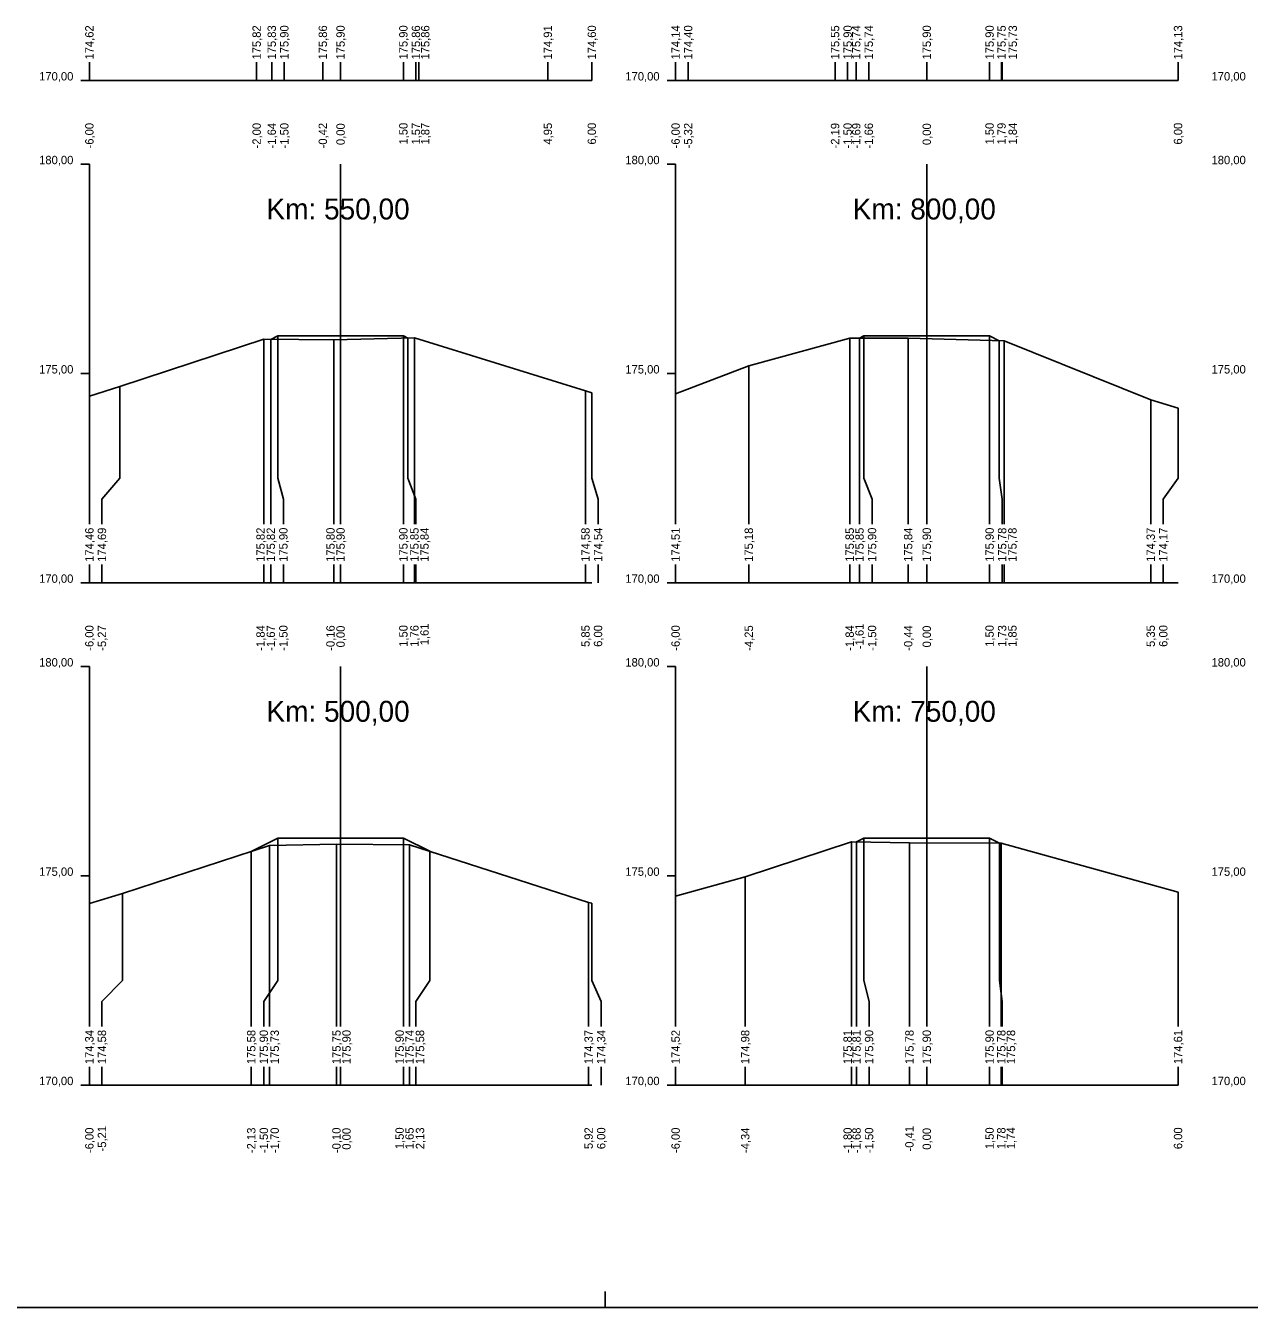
# Model space of a CAD drawing. Extents: x -614174 to -599765, y -1185887 to -1181080.
# Drawn here: x -612663.55 to -612634.33, y -1184252.54 to -1184221.92 of the extents above; entities that cross this region are included whole.
import ezdxf

# ---------------------------------------------------------------- set-up
doc = ezdxf.new("R2010")
doc.units = 0
for name, color, linetype in [('11', 7, 'Continuous'), ('16', 7, 'Continuous'), ('21', 7, 'Continuous'), ('28', 7, 'Continuous'), ('59', 7, 'Continuous'), ('8', 7, 'Continuous'), ('návrh', 7, 'Continuous')]:
    doc.layers.add(name, color=color, linetype=linetype)

msp = doc.modelspace()

# ---------------------------------------------------------------- linework, layer by layer
for points in [[(-612662.029, -1184230.778), (-612661.299, -1184230.541), (-612657.865, -1184229.416), (-612656.188, -1184229.431), (-612654.266, -1184229.385), (-612650.181, -1184230.651), (-612650.029, -1184230.697)], [(-612657.696, -1184229.418), (-612657.53, -1184229.335), (-612656.03, -1184229.335), (-612654.53, -1184229.335), (-612654.421, -1184229.389)], [(-612657.696, -1184229.418), (-612657.696, -1184229.418), (-612657.696, -1184229.418)], [(-612657.53, -1184229.335), (-612657.53, -1184229.335)], [(-612656.03, -1184229.335), (-612656.03, -1184229.335)], [(-612654.53, -1184229.335), (-612654.53, -1184229.335)], [(-612648.029, -1184230.72), (-612646.281, -1184230.054), (-612643.871, -1184229.388), (-612642.474, -1184229.392), (-612640.178, -1184229.453), (-612636.682, -1184230.863), (-612636.029, -1184231.066)], [(-612643.637, -1184229.388), (-612643.53, -1184229.335), (-612642.03, -1184229.335), (-612640.53, -1184229.335), (-612640.3, -1184229.45)], [(-612643.637, -1184229.388), (-612643.637, -1184229.388), (-612643.637, -1184229.388)], [(-612643.53, -1184229.335), (-612643.53, -1184229.335)], [(-612642.03, -1184229.335), (-612642.03, -1184229.335)], [(-612640.53, -1184229.335), (-612640.53, -1184229.335)], [(-612662.029, -1184242.896), (-612661.238, -1184242.657), (-612657.728, -1184241.509), (-612656.128, -1184241.479), (-612654.384, -1184241.494), (-612650.106, -1184242.868), (-612650.029, -1184242.891)], [(-612658.163, -1184241.651), (-612657.53, -1184241.335), (-612656.03, -1184241.335), (-612654.53, -1184241.335), (-612653.9, -1184241.649)], [(-612657.53, -1184241.335), (-612657.53, -1184241.335)], [(-612656.03, -1184241.335), (-612656.03, -1184241.335)], [(-612654.53, -1184241.335), (-612654.53, -1184241.335)], [(-612648.029, -1184242.717), (-612646.366, -1184242.257), (-612643.825, -1184241.421), (-612642.444, -1184241.449), (-612640.25, -1184241.455), (-612636.029, -1184242.628)], [(-612643.708, -1184241.424), (-612643.53, -1184241.335), (-612642.03, -1184241.335), (-612640.53, -1184241.335), (-612640.289, -1184241.455)], [(-612643.708, -1184241.424), (-612643.708, -1184241.424), (-612643.708, -1184241.424)], [(-612643.53, -1184241.335), (-612643.53, -1184241.335)], [(-612642.03, -1184241.335), (-612642.03, -1184241.335)], [(-612640.53, -1184241.335), (-612640.53, -1184241.335)], [(-612658.163, -1184241.651), (-612658.163, -1184241.651), (-612658.163, -1184241.651)]]:
    msp.add_lwpolyline(points)
at = {"layer": '11'}
for points in [[(-612662.029, -1184222.794), (-612662.029, -1184223.234)], [(-612658.034, -1184222.794), (-612658.034, -1184223.234)], [(-612657.673, -1184222.794), (-612657.673, -1184223.234)], [(-612657.373, -1184222.794), (-612657.373, -1184223.234)], [(-612656.454, -1184222.794), (-612656.454, -1184223.234)], [(-612656.03, -1184222.794), (-612656.03, -1184223.234)], [(-612654.53, -1184222.794), (-612654.53, -1184223.234)], [(-612654.23, -1184222.794), (-612654.23, -1184223.234)], [(-612654.163, -1184222.794), (-612654.163, -1184223.234)], [(-612651.08, -1184222.794), (-612651.08, -1184223.234)], [(-612650.029, -1184222.794), (-612650.029, -1184223.234)], [(-612648.029, -1184222.794), (-612648.029, -1184223.234)], [(-612647.729, -1184222.794), (-612647.729, -1184223.234)], [(-612644.22, -1184222.794), (-612644.22, -1184223.234)], [(-612643.92, -1184222.794), (-612643.92, -1184223.234)], [(-612643.715, -1184222.794), (-612643.715, -1184223.234)], [(-612643.415, -1184222.794), (-612643.415, -1184223.234)], [(-612642.03, -1184222.794), (-612642.03, -1184223.234)], [(-612640.53, -1184222.794), (-612640.53, -1184223.234)], [(-612640.244, -1184222.794), (-612640.244, -1184223.234)], [(-612640.23, -1184222.794), (-612640.23, -1184223.234)], [(-612636.029, -1184222.794), (-612636.029, -1184223.234)], [(-612657.865, -1184229.416), (-612657.865, -1184232.734), (-612657.865, -1184233.234), (-612657.865, -1184233.835)], [(-612657.696, -1184229.418), (-612657.696, -1184232.734), (-612657.696, -1184233.234), (-612657.696, -1184233.835)], [(-612657.53, -1184229.335), (-612657.53, -1184232.734), (-612657.396, -1184233.234), (-612657.396, -1184233.835)], [(-612656.188, -1184229.431), (-612656.188, -1184232.734), (-612656.188, -1184233.234), (-612656.188, -1184233.835)], [(-612656.03, -1184229.335), (-612656.03, -1184232.734), (-612656.03, -1184233.234), (-612656.03, -1184233.835)], [(-612654.53, -1184229.335), (-612654.53, -1184232.734), (-612654.53, -1184233.234), (-612654.53, -1184233.835)], [(-612654.421, -1184229.389), (-612654.421, -1184232.734), (-612654.23, -1184233.234), (-612654.23, -1184233.835)], [(-612654.266, -1184229.385), (-612654.266, -1184232.734), (-612654.266, -1184233.234), (-612654.266, -1184233.835)], [(-612643.871, -1184229.388), (-612643.871, -1184232.734), (-612643.871, -1184233.234), (-612643.871, -1184233.835)], [(-612643.637, -1184229.388), (-612643.637, -1184232.734), (-612643.637, -1184233.234), (-612643.637, -1184233.835)], [(-612643.53, -1184229.335), (-612643.53, -1184232.734), (-612643.337, -1184233.234), (-612643.337, -1184233.835)], [(-612642.474, -1184229.392), (-612642.474, -1184232.734), (-612642.474, -1184233.234), (-612642.474, -1184233.835)], [(-612642.03, -1184229.335), (-612642.03, -1184232.734), (-612642.03, -1184233.234), (-612642.03, -1184233.835)], [(-612640.53, -1184229.335), (-612640.53, -1184232.734), (-612640.53, -1184233.234), (-612640.53, -1184233.835)], [(-612640.3, -1184229.45), (-612640.3, -1184232.734), (-612640.23, -1184233.234), (-612640.23, -1184233.835)], [(-612640.178, -1184229.453), (-612640.178, -1184232.734), (-612640.178, -1184233.234), (-612640.178, -1184233.835)], [(-612646.281, -1184230.054), (-612646.281, -1184232.734), (-612646.281, -1184233.234), (-612646.281, -1184233.835)], [(-612662.029, -1184230.778), (-612662.029, -1184232.734), (-612662.029, -1184233.234), (-612662.029, -1184233.835)], [(-612661.299, -1184230.541), (-612661.299, -1184232.734), (-612661.729, -1184233.234), (-612661.729, -1184233.835)], [(-612650.181, -1184230.651), (-612650.181, -1184232.734), (-612650.181, -1184233.234), (-612650.181, -1184233.835)], [(-612650.029, -1184230.697), (-612650.029, -1184232.734), (-612649.881, -1184233.234), (-612649.881, -1184233.835)], [(-612648.029, -1184230.72), (-612648.029, -1184232.734), (-612648.029, -1184233.234), (-612648.029, -1184233.835)], [(-612636.682, -1184230.863), (-612636.682, -1184232.734), (-612636.682, -1184233.234), (-612636.682, -1184233.835)], [(-612636.029, -1184231.066), (-612636.029, -1184232.734), (-612636.382, -1184233.234), (-612636.382, -1184233.835)], [(-612662.029, -1184234.794), (-612662.029, -1184235.234)], [(-612661.729, -1184234.794), (-612661.729, -1184235.234)], [(-612657.865, -1184234.794), (-612657.865, -1184235.234)], [(-612657.696, -1184234.794), (-612657.696, -1184235.234)], [(-612657.396, -1184234.794), (-612657.396, -1184235.234)], [(-612656.188, -1184234.794), (-612656.188, -1184235.234)], [(-612656.03, -1184234.794), (-612656.03, -1184235.234)], [(-612654.53, -1184234.794), (-612654.53, -1184235.234)], [(-612654.266, -1184234.794), (-612654.266, -1184235.234)], [(-612654.23, -1184234.794), (-612654.23, -1184235.234)], [(-612650.181, -1184234.794), (-612650.181, -1184235.234)], [(-612649.881, -1184234.794), (-612649.881, -1184235.234)], [(-612648.029, -1184234.794), (-612648.029, -1184235.234)], [(-612646.281, -1184234.794), (-612646.281, -1184235.234)], [(-612643.871, -1184234.794), (-612643.871, -1184235.234)], [(-612643.637, -1184234.794), (-612643.637, -1184235.234)], [(-612643.337, -1184234.794), (-612643.337, -1184235.234)], [(-612642.474, -1184234.794), (-612642.474, -1184235.234)], [(-612642.03, -1184234.794), (-612642.03, -1184235.234)], [(-612640.53, -1184234.794), (-612640.53, -1184235.234)], [(-612640.23, -1184234.794), (-612640.23, -1184235.234)], [(-612640.178, -1184234.794), (-612640.178, -1184235.234)], [(-612636.682, -1184234.794), (-612636.682, -1184235.234)], [(-612636.382, -1184234.794), (-612636.382, -1184235.234)], [(-612657.53, -1184241.335), (-612657.53, -1184244.734), (-612657.863, -1184245.234), (-612657.863, -1184245.835)], [(-612657.728, -1184241.509), (-612657.728, -1184244.734), (-612657.728, -1184245.234), (-612657.728, -1184245.835)], [(-612656.128, -1184241.479), (-612656.128, -1184244.734), (-612656.128, -1184245.234), (-612656.128, -1184245.835)], [(-612656.03, -1184241.335), (-612656.03, -1184244.734), (-612656.03, -1184245.234), (-612656.03, -1184245.835)], [(-612654.53, -1184241.335), (-612654.53, -1184244.734), (-612654.53, -1184245.234), (-612654.53, -1184245.835)], [(-612654.384, -1184241.494), (-612654.384, -1184244.734), (-612654.384, -1184245.234), (-612654.384, -1184245.835)], [(-612643.825, -1184241.421), (-612643.825, -1184244.734), (-612643.825, -1184245.234), (-612643.825, -1184245.835)], [(-612643.708, -1184241.424), (-612643.708, -1184244.734), (-612643.708, -1184245.234), (-612643.708, -1184245.835)], [(-612643.53, -1184241.335), (-612643.53, -1184244.734), (-612643.408, -1184245.234), (-612643.408, -1184245.835)], [(-612642.444, -1184241.449), (-612642.444, -1184244.734), (-612642.444, -1184245.234), (-612642.444, -1184245.835)], [(-612642.03, -1184241.335), (-612642.03, -1184244.734), (-612642.03, -1184245.234), (-612642.03, -1184245.835)], [(-612640.53, -1184241.335), (-612640.53, -1184244.734), (-612640.53, -1184245.234), (-612640.53, -1184245.835)], [(-612640.289, -1184241.455), (-612640.289, -1184244.734), (-612640.23, -1184245.234), (-612640.23, -1184245.835)], [(-612640.25, -1184241.455), (-612640.25, -1184244.734), (-612640.25, -1184245.234), (-612640.25, -1184245.835)], [(-612658.163, -1184241.651), (-612658.163, -1184244.734), (-612658.163, -1184245.234), (-612658.163, -1184245.835)], [(-612653.9, -1184241.649), (-612653.9, -1184244.734), (-612654.23, -1184245.234), (-612654.23, -1184245.835)], [(-612646.366, -1184242.257), (-612646.366, -1184244.734), (-612646.366, -1184245.234), (-612646.366, -1184245.835)], [(-612661.238, -1184242.657), (-612661.238, -1184244.734), (-612661.729, -1184245.234), (-612661.729, -1184245.835)], [(-612648.029, -1184242.717), (-612648.029, -1184244.734), (-612648.029, -1184245.234), (-612648.029, -1184245.835)], [(-612636.029, -1184242.628), (-612636.029, -1184244.734), (-612636.029, -1184245.234), (-612636.029, -1184245.835)], [(-612662.029, -1184242.896), (-612662.029, -1184244.734), (-612662.029, -1184245.234), (-612662.029, -1184245.835)], [(-612650.106, -1184242.868), (-612650.106, -1184244.734), (-612650.106, -1184245.234), (-612650.106, -1184245.835)], [(-612650.029, -1184242.891), (-612650.029, -1184244.734), (-612649.806, -1184245.234), (-612649.806, -1184245.835)], [(-612662.029, -1184246.794), (-612662.029, -1184247.234)], [(-612661.729, -1184246.794), (-612661.729, -1184247.234)], [(-612658.163, -1184246.794), (-612658.163, -1184247.234)], [(-612657.863, -1184246.794), (-612657.863, -1184247.234)], [(-612657.728, -1184246.794), (-612657.728, -1184247.234)], [(-612656.128, -1184246.794), (-612656.128, -1184247.234)], [(-612656.03, -1184246.794), (-612656.03, -1184247.234)], [(-612654.53, -1184246.794), (-612654.53, -1184247.234)], [(-612654.384, -1184246.794), (-612654.384, -1184247.234)], [(-612654.23, -1184246.794), (-612654.23, -1184247.234)], [(-612650.106, -1184246.794), (-612650.106, -1184247.234)], [(-612649.806, -1184246.794), (-612649.806, -1184247.234)], [(-612648.029, -1184246.794), (-612648.029, -1184247.234)], [(-612646.366, -1184246.794), (-612646.366, -1184247.234)], [(-612643.825, -1184246.794), (-612643.825, -1184247.234)], [(-612643.708, -1184246.794), (-612643.708, -1184247.234)], [(-612643.408, -1184246.794), (-612643.408, -1184247.234)], [(-612642.444, -1184246.794), (-612642.444, -1184247.234)], [(-612642.03, -1184246.794), (-612642.03, -1184247.234)], [(-612640.53, -1184246.794), (-612640.53, -1184247.234)], [(-612640.25, -1184246.794), (-612640.25, -1184247.234)], [(-612640.23, -1184246.794), (-612640.23, -1184247.234)], [(-612636.029, -1184246.794), (-612636.029, -1184247.234)]]:
    msp.add_lwpolyline(points, dxfattribs=at)
at = {"layer": '16'}
for p, q in [((-612662.029, -1184223.234), (-612650.029, -1184223.234)), ((-612648.029, -1184223.234), (-612636.029, -1184223.234)), ((-612662.029, -1184235.234), (-612650.029, -1184235.234)), ((-612648.029, -1184235.234), (-612636.029, -1184235.234)), ((-612662.029, -1184247.234), (-612650.029, -1184247.234)), ((-612648.029, -1184247.234), (-612636.029, -1184247.234))]:
    msp.add_line(p, q, dxfattribs=at)
for points in [[(-612654.421, -1184229.389), (-612654.421, -1184229.389), (-612654.421, -1184229.389)], [(-612640.3, -1184229.45), (-612640.3, -1184229.45), (-612640.3, -1184229.45)], [(-612640.289, -1184241.455), (-612640.289, -1184241.455), (-612640.289, -1184241.455)], [(-612653.9, -1184241.649), (-612653.9, -1184241.649), (-612653.9, -1184241.649)]]:
    msp.add_lwpolyline(points, dxfattribs=at)
at = {"layer": '21'}
for p, q in [((-612662.229, -1184223.234), (-612662.029, -1184223.234)), ((-612648.229, -1184223.234), (-612648.029, -1184223.234)), ((-612662.229, -1184225.234), (-612662.029, -1184225.234)), ((-612648.229, -1184225.234), (-612648.029, -1184225.234)), ((-612662.229, -1184230.234), (-612662.029, -1184230.234)), ((-612648.229, -1184230.234), (-612648.029, -1184230.234)), ((-612662.229, -1184235.234), (-612662.029, -1184235.234)), ((-612648.229, -1184235.234), (-612648.029, -1184235.234)), ((-612662.229, -1184237.234), (-612662.029, -1184237.234)), ((-612648.229, -1184237.234), (-612648.029, -1184237.234)), ((-612662.229, -1184242.234), (-612662.029, -1184242.234)), ((-612648.229, -1184242.234), (-612648.029, -1184242.234)), ((-612662.229, -1184247.234), (-612662.029, -1184247.234)), ((-612648.229, -1184247.234), (-612648.029, -1184247.234))]:
    msp.add_line(p, q, dxfattribs=at)
at = {"layer": '28'}
for p, q in [((-612656.029, -1184223.234), (-612656.029, -1184222.794)), ((-612642.029, -1184223.234), (-612642.029, -1184222.794)), ((-612656.029, -1184233.835), (-612656.029, -1184225.234)), ((-612642.029, -1184233.835), (-612642.029, -1184225.234)), ((-612656.029, -1184235.234), (-612656.029, -1184234.794)), ((-612642.029, -1184235.234), (-612642.029, -1184234.794)), ((-612656.029, -1184245.835), (-612656.029, -1184237.234)), ((-612642.029, -1184245.835), (-612642.029, -1184237.234)), ((-612656.029, -1184247.234), (-612656.029, -1184246.794)), ((-612642.029, -1184247.234), (-612642.029, -1184246.794))]:
    msp.add_line(p, q, dxfattribs=at)
at = {"layer": '8'}
for p, q in [((-612662.029, -1184223.234), (-612662.029, -1184222.794)), ((-612648.029, -1184223.234), (-612648.029, -1184222.794)), ((-612662.029, -1184233.835), (-612662.029, -1184225.234)), ((-612648.029, -1184233.835), (-612648.029, -1184225.234)), ((-612662.029, -1184235.234), (-612662.029, -1184234.794)), ((-612648.029, -1184235.234), (-612648.029, -1184234.794)), ((-612662.029, -1184245.835), (-612662.029, -1184237.234)), ((-612648.029, -1184245.835), (-612648.029, -1184237.234)), ((-612662.029, -1184247.234), (-612662.029, -1184246.794)), ((-612648.029, -1184247.234), (-612648.029, -1184246.794))]:
    msp.add_line(p, q, dxfattribs=at)
at = {"layer": 'návrh'}
for p, q in [((-612649.713, -1184252.543), (-612649.713, -1184252.163)), ((-612670.713, -1184252.543), (-612649.713, -1184252.543)), ((-612649.713, -1184252.543), (-612628.713, -1184252.543))]:
    msp.add_line(p, q, dxfattribs=at)

# ---------------------------------------------------------------- texts
at = {"layer": '16'}
for s, p in [('174,62', (-612661.929, -1184222.734)), ('175,82', (-612657.934, -1184222.734)), ('175,83', (-612657.573, -1184222.734)), ('175,90', (-612657.273, -1184222.734)), ('175,86', (-612656.354, -1184222.734)), ('175,90', (-612655.93, -1184222.734)), ('175,90', (-612654.43, -1184222.734)), ('175,86', (-612654.13, -1184222.734)), ('175,86', (-612653.908, -1184222.734)), ('174,91', (-612650.98, -1184222.734)), ('174,60', (-612649.929, -1184222.734)), ('174,14', (-612647.929, -1184222.734)), ('174,40', (-612647.629, -1184222.734)), ('175,55', (-612644.12, -1184222.734)), ('175,90', (-612643.82, -1184222.734)), ('175,74', (-612643.615, -1184222.734)), ('175,74', (-612643.315, -1184222.734)), ('175,90', (-612641.93, -1184222.734)), ('175,90', (-612640.43, -1184222.734)), ('175,75', (-612640.144, -1184222.734)), ('175,73', (-612639.877, -1184222.734)), ('174,13', (-612635.929, -1184222.734)), ('174,46', (-612661.929, -1184234.734)), ('174,69', (-612661.629, -1184234.734)), ('175,82', (-612657.841, -1184234.734)), ('175,82', (-612657.596, -1184234.734)), ('175,90', (-612657.296, -1184234.734)), ('175,80', (-612656.171, -1184234.734)), ('175,90', (-612655.93, -1184234.734)), ('175,90', (-612654.43, -1184234.734)), ('175,85', (-612654.166, -1184234.734)), ('175,84', (-612653.926, -1184234.734)), ('174,58', (-612650.081, -1184234.734)), ('174,54', (-612649.781, -1184234.734)), ('174,51', (-612647.929, -1184234.734)), ('175,18', (-612646.181, -1184234.734)), ('175,85', (-612643.771, -1184234.734)), ('175,85', (-612643.537, -1184234.734)), ('175,90', (-612643.237, -1184234.734)), ('175,84', (-612642.374, -1184234.734)), ('175,90', (-612641.93, -1184234.734)), ('175,90', (-612640.43, -1184234.734)), ('175,78', (-612640.13, -1184234.734)), ('175,78', (-612639.885, -1184234.734)), ('174,37', (-612636.582, -1184234.734)), ('174,17', (-612636.282, -1184234.734)), ('174,34', (-612661.929, -1184246.734)), ('174,58', (-612661.629, -1184246.734)), ('175,58', (-612658.063, -1184246.734)), ('175,90', (-612657.763, -1184246.734)), ('175,73', (-612657.503, -1184246.734)), ('175,75', (-612656.028, -1184246.734)), ('175,90', (-612655.788, -1184246.734)), ('175,90', (-612654.52, -1184246.734)), ('175,74', (-612654.284, -1184246.734)), ('175,58', (-612654.033, -1184246.734)), ('174,37', (-612650.006, -1184246.734)), ('174,34', (-612649.706, -1184246.734)), ('174,52', (-612647.929, -1184246.734)), ('174,98', (-612646.266, -1184246.734)), ('175,81', (-612643.819, -1184246.734)), ('175,81', (-612643.608, -1184246.734)), ('175,90', (-612643.308, -1184246.734)), ('175,78', (-612642.344, -1184246.734)), ('175,90', (-612641.93, -1184246.734)), ('175,90', (-612640.43, -1184246.734)), ('175,78', (-612640.15, -1184246.734)), ('175,78', (-612639.919, -1184246.734)), ('174,61', (-612635.929, -1184246.734))]:
    msp.add_text(s, height=0.2, rotation=90, dxfattribs=at).set_placement(p)
at = {"layer": '21'}
for s, p in [('170,00', (-612663.229, -1184223.234)), ('170,00', (-612649.229, -1184223.234)), ('170,00', (-612635.229, -1184223.234)), ('180,00', (-612663.229, -1184225.234)), ('180,00', (-612649.229, -1184225.234)), ('180,00', (-612635.229, -1184225.234)), ('175,00', (-612663.229, -1184230.234)), ('175,00', (-612649.229, -1184230.234)), ('175,00', (-612635.229, -1184230.234)), ('170,00', (-612663.229, -1184235.234)), ('170,00', (-612649.229, -1184235.234)), ('170,00', (-612635.229, -1184235.234)), ('180,00', (-612663.229, -1184237.234)), ('180,00', (-612649.229, -1184237.234)), ('180,00', (-612635.229, -1184237.234)), ('175,00', (-612663.229, -1184242.234)), ('175,00', (-612649.229, -1184242.234)), ('175,00', (-612635.229, -1184242.234)), ('170,00', (-612663.229, -1184247.234)), ('170,00', (-612649.229, -1184247.234)), ('170,00', (-612635.229, -1184247.234))]:
    msp.add_text(s, height=0.2, dxfattribs=at).set_placement(p)
at = {"layer": '28'}
for s, p in [('Km: 550,00', (-612657.799, -1184226.554)), ('Km: 800,00', (-612643.799, -1184226.554)), ('Km: 500,00', (-612657.799, -1184238.554)), ('Km: 750,00', (-612643.799, -1184238.554))]:
    msp.add_text(s, height=0.5, dxfattribs=at).set_placement(p)
at = {"layer": '59'}
for s, p in [('-6,00', (-612661.929, -1184224.857)), ('-2,00', (-612657.934, -1184224.857)), ('-1,64', (-612657.573, -1184224.857)), ('-1,50', (-612657.273, -1184224.857)), ('-0,42', (-612656.354, -1184224.856)), ('0,00', (-612655.93, -1184224.777)), ('1,50', (-612654.43, -1184224.764)), ('1,57', (-612654.13, -1184224.765)), ('1,87', (-612653.908, -1184224.765)), ('4,95', (-612650.98, -1184224.766)), ('6,00', (-612649.929, -1184224.764)), ('-6,00', (-612647.929, -1184224.857)), ('-5,32', (-612647.629, -1184224.856)), ('-2,19', (-612644.12, -1184224.858)), ('-1,50', (-612643.82, -1184224.857)), ('-1,69', (-612643.615, -1184224.858)), ('-1,66', (-612643.315, -1184224.858)), ('0,00', (-612641.93, -1184224.777)), ('1,50', (-612640.43, -1184224.764)), ('1,79', (-612640.144, -1184224.765)), ('1,84', (-612639.877, -1184224.764)), ('6,00', (-612635.929, -1184224.764)), ('-6,00', (-612661.929, -1184236.857)), ('-5,27', (-612661.629, -1184236.858)), ('-1,84', (-612657.841, -1184236.857)), ('-1,67', (-612657.596, -1184236.858)), ('-1,50', (-612657.296, -1184236.857)), ('-0,16', (-612656.171, -1184236.858)), ('0,00', (-612655.93, -1184236.777)), ('1,50', (-612654.43, -1184236.764)), ('1,76', (-612654.166, -1184236.765)), ('1,61', (-612653.926, -1184236.726)), ('5,85', (-612650.081, -1184236.766)), ('6,00', (-612649.781, -1184236.764)), ('-6,00', (-612647.929, -1184236.857)), ('-4,25', (-612646.181, -1184236.859)), ('-1,84', (-612643.771, -1184236.857)), ('-1,61', (-612643.537, -1184236.819)), ('-1,50', (-612643.237, -1184236.857)), ('-0,44', (-612642.374, -1184236.857)), ('0,00', (-612641.93, -1184236.777)), ('1,50', (-612640.43, -1184236.764)), ('1,73', (-612640.13, -1184236.765)), ('1,85', (-612639.885, -1184236.766)), ('5,35', (-612636.582, -1184236.766)), ('6,00', (-612636.282, -1184236.764)), ('-6,00', (-612661.929, -1184248.857)), ('-5,21', (-612661.629, -1184248.819)), ('-2,13', (-612658.063, -1184248.858)), ('-1,50', (-612657.763, -1184248.857)), ('-1,70', (-612657.503, -1184248.857)), ('-0,10', (-612656.028, -1184248.857)), ('0,00', (-612655.788, -1184248.777)), ('1,50', (-612654.52, -1184248.764)), ('1,65', (-612654.284, -1184248.766)), ('2,13', (-612654.033, -1184248.765)), ('5,92', (-612650.006, -1184248.763)), ('6,00', (-612649.706, -1184248.764)), ('-6,00', (-612647.929, -1184248.857)), ('-4,34', (-612646.266, -1184248.857)), ('-1,80', (-612643.819, -1184248.857)), ('-1,68', (-612643.608, -1184248.858)), ('-1,50', (-612643.308, -1184248.857)), ('-0,41', (-612642.344, -1184248.819)), ('0,00', (-612641.93, -1184248.777)), ('1,50', (-612640.43, -1184248.764)), ('1,78', (-612640.15, -1184248.765)), ('1,74', (-612639.919, -1184248.764)), ('6,00', (-612635.929, -1184248.764))]:
    msp.add_text(s, height=0.2, rotation=90, dxfattribs=at).set_placement(p)

doc.saveas('drawing.dxf')
